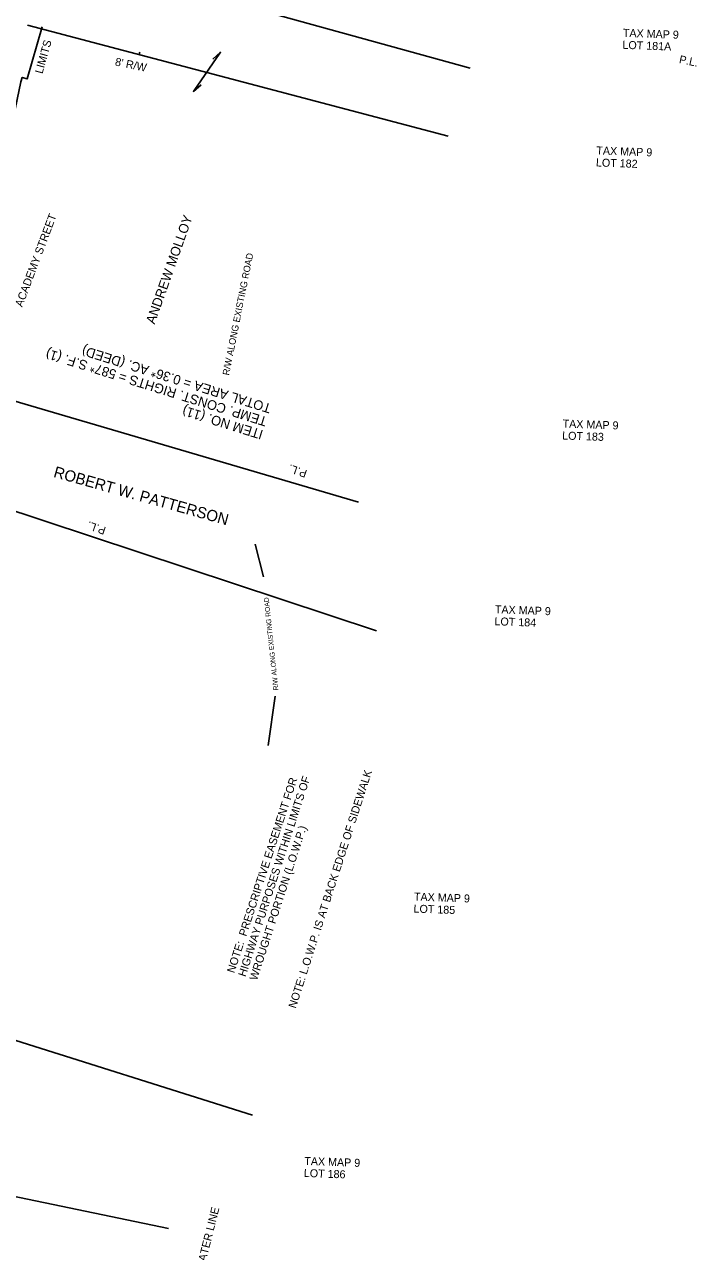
# Model space of a CAD drawing. Extents: x 1133267 to 1139526, y 528613 to 531538.
# Drawn here: x 1137366.3 to 1137576.2, y 529193.4 to 529576.6 of the extents above; entities that cross this region are included whole.
import ezdxf

# ---------------------------------------------------------------- set-up
doc = ezdxf.new("R2010")
doc.units = 0
for name, color, linetype in [('E_Property_Line', 7, 'Continuous'), ('E_Property_LotLine', 7, 'Continuous'), ('E_ROW_TieLine', 7, 'Continuous'), ('EX ROW NOTES', 7, 'Continuous'), ('LOW WATER LINE', 7, 'Continuous'), ('MISCELLN TEXT', 7, 'Continuous'), ('P_Ease_Temp_Grading_Line', 7, 'Continuous'), ('PROPERTY LINES', 7, 'Continuous'), ('PROPERTY NOTES', 7, 'Continuous'), ('PRP OWNER NAMES', 7, 'Continuous'), ('PRPTY SETUPS', 7, 'Continuous'), ('TEMP RIGHTS', 7, 'Continuous')]:
    doc.layers.add(name, color=color, linetype=linetype)

msp = doc.modelspace()

# ---------------------------------------------------------------- linework, layer by layer
at = {"layer": 'E_Property_Line'}
for p, q in [((1137371.08, 529600.14), (1137505.47, 529563.04)), ((1137419.03, 529555.74), (1137427.53, 529568)), ((1137326.24, 529469.89), (1137470.64, 529427.51)), ((1137315.72, 529440.34), (1137476.28, 529387.28)), ((1137262.82, 529291.06), (1137437.52, 529235.95))]:
    msp.add_line(p, q, dxfattribs=at)
for points in [[(1137425.11, 529565.87), (1137427.53, 529568), (1137427.53, 529568), (1137425.75, 529565.43)], [(1137421.45, 529557.86), (1137419.03, 529555.74), (1137419.03, 529555.74), (1137420.81, 529558.3)], [(1137242.99, 529235.55), (1137411.29, 529200.58)]]:
    msp.add_lwpolyline(points, dxfattribs=at)
at = {"layer": 'E_Property_LotLine'}
msp.add_line((1137367.22, 529576.45), (1137498.59, 529541.76), dxfattribs=at)
at = {"layer": 'E_ROW_TieLine'}
for p, q in [((1137402.27, 529568.01), (1137402.05, 529567.24)), ((1137440.97, 529404.16), (1137438.34, 529414.34)), ((1137444.55, 529366.91), (1137442.4, 529351.48))]:
    msp.add_line(p, q, dxfattribs=at)
at = {"layer": 'P_Ease_Temp_Grading_Line'}
msp.add_lwpolyline([(1137342.73, 529468.66), (1137345.93, 529481.81), (1137351.6, 529505.21), (1137360.56, 529536.67), (1137365.09, 529558.71), (1137365.54, 529560.14), (1137367.1, 529559.66), (1137371.74, 529575.97)], dxfattribs=at)

# ---------------------------------------------------------------- texts
at = {"layer": 'EX ROW NOTES'}
for s, p in [('HIGHWAY PURPOSES WITHIN LIMITS OF', (1137435.32, 529279.04)), ('NOTE:  PRESCRIPTIVE EASEMENT FOR', (1137431.8, 529280.19)), ('WROUGHT PORTION (L.O.W.P.)', (1137438.84, 529277.9))]:
    msp.add_text(s, height=2.5, rotation=72.0047, dxfattribs=at).set_placement(p)
at = {"layer": 'LOW WATER LINE'}
msp.add_text('LOW WATER LINE ', height=2.5, rotation=75.8014, dxfattribs=at).set_placement((1137420.06, 529178.82))
at = {"layer": 'MISCELLN TEXT'}
for s, height, rotation, p in [('ACADEMY STREET', 2.5, 69.3867, (1137365.55, 529488.25)), ('NOTE: L.O.W.P. IS AT BACK EDGE OF SIDEWALK', 2.49, 72.1796, (1137451.01, 529269.17))]:
    msp.add_text(s, height=height, rotation=rotation, dxfattribs=at).set_placement(p)
at = {"layer": 'PROPERTY LINES'}
for rotation, p in [(348.3631, (1137570.62, 529564.64)), (160.8152, (1137454.75, 529437.38)), (160.8152, (1137391.9, 529419.58))]:
    msp.add_text('P.L.', height=2.49, rotation=rotation, dxfattribs=at).set_placement(p)
at = {"layer": 'PROPERTY NOTES'}
for s, height, rotation, p in [('TAX MAP 9', 2.5, 357.9281, (1137553.18, 529572.83)), ('LOT 181A', 2.5, 357.9281, (1137553.04, 529569.08)), ("8' R/W", 2.5, 348.6223, (1137394.4, 529563.88)), ('TAX MAP 9', 2.5, 357.9281, (1137544.89, 529536.09)), ('LOT 182', 2.5, 357.9281, (1137544.76, 529532.34)), ('R/W ALONG EXISTING ROAD', 2.1, 78.7031, (1137430.15, 529466.94)), ('TAX MAP 9', 2.5, 357.9281, (1137534.35, 529450.79)), ('LOT 183', 2.5, 357.9281, (1137534.21, 529447.05)), ('R/W ALONG EXISTING ROAD', 1.53, 96.0194, (1137445.6, 529368.73)), ('LOT 184', 2.5, 357.9281, (1137513.06, 529389.03)), ('TAX MAP 9', 2.5, 357.9281, (1137513.19, 529392.77)), ('TAX MAP 9', 2.5, 357.9281, (1137487.91, 529303.03)), ('LOT 185', 2.5, 357.9281, (1137487.77, 529299.28)), ('TAX MAP 9', 2.5, 357.9281, (1137453.64, 529220.45)), ('LOT 186', 2.5, 357.9281, (1137453.5, 529216.7))]:
    msp.add_text(s, height=height, rotation=rotation, dxfattribs=at).set_placement(p)
at = {"layer": 'PRP OWNER NAMES'}
for s, height, rotation, p in [('ANDREW MOLLOY', 3, 70.4661, (1137406.91, 529482.85)), ('ROBERT W. PATTERSON', 3.5, 344.4065, (1137375.1, 529435.36))]:
    msp.add_text(s, height=height, rotation=rotation, dxfattribs=at).set_placement(p)
at = {"layer": 'PRPTY SETUPS'}
for s, p in [('TEMP. CONST. RIGHTS = 587* S.F. (1)', (1137442.32, 529453.93)), ('TOTAL AREA = 0.36* AC. (DEED)', (1137443.6, 529458.02)), ('ITEM NO. (11)', (1137441.05, 529449.83))]:
    msp.add_text(s, height=3, rotation=162.6813, dxfattribs=at).set_placement(p)
at = {"layer": 'TEMP RIGHTS'}
msp.add_text('LIMITS', height=2.49, rotation=74.3632, dxfattribs=at).set_placement((1137371.86, 529561.1))

doc.saveas('drawing.dxf')
